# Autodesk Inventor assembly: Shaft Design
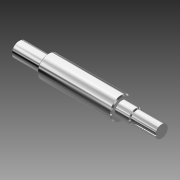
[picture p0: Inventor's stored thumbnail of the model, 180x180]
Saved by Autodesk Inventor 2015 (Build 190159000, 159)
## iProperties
Created: 2007-02
Part Number: Shaft Design
Document SubType Name: Assembly
Designer: Autodesk, Inc.
Mass: 5212.32 g
Surface Area: 583.464 cm^2
Volume: 663.99 cm^3
Density: 7.85 g/cm^3
ClientObjectVersion: 1
Author: Autodesk, Inc.
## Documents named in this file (2)
- C:\Users\Public\Documents\Autodesk\Inventor 2015\Samples\Models\Assemblies\Blower\Motor Assembly\Design Accelerator\Shaft1.iam
- C:\Users\Public\Documents\Autodesk\Inventor 2015\Samples\Models\Assemblies\Blower\Motor Assembly\Design Accelerator\Shaft1.ipt
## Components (1 placed, 1 different names)
1. Motor Shaft 001:1
